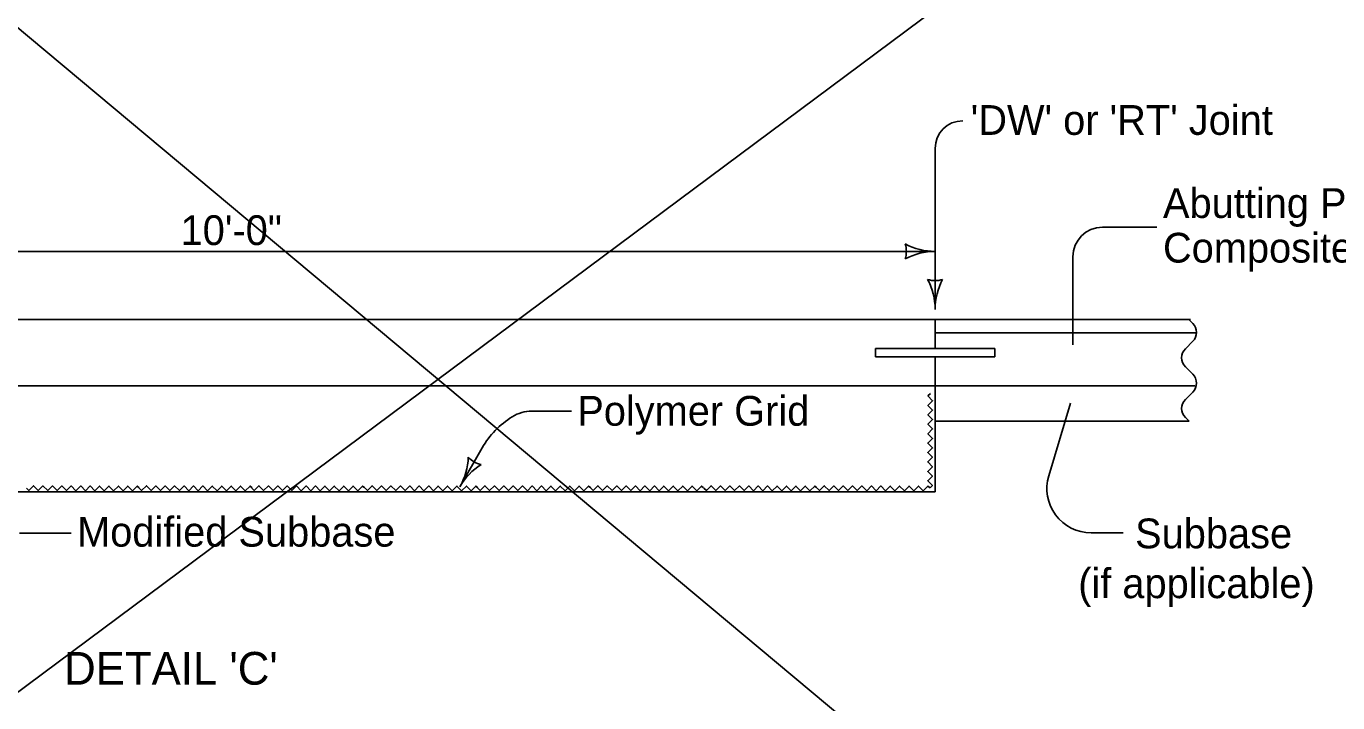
# Model space of a CAD drawing. Extents: x 8925 to 81668, y 4369 to 11918.
# Drawn here: x 14969 to 15851, y 5831 to 6286 of the extents above; entities that cross this region are included whole.
import ezdxf

# ---------------------------------------------------------------- set-up
doc = ezdxf.new("R2010")
doc.units = 0
for name, color, linetype in [('dsnShtPlotShapeBatchPrint', 7, 'Continuous'), ('dsnStdBorder', 7, 'Continuous'), ('SheetBorder', 7, 'Continuous')]:
    doc.layers.add(name, color=color, linetype=linetype)

msp = doc.modelspace()

# ---------------------------------------------------------------- linework, layer by layer
at = {"layer": 'dsnStdBorder'}
for p, q in [((15580.02, 6095.61), (15580.02, 6203.81)), ((15729, 6150.84), (15692.53, 6150.84)), ((14653.38, 6134.57), (15580.02, 6134.57)), ((15672.73, 6131.04), (15672.73, 6071.75)), ((15580.02, 6088.81), (14663.54, 6088.81)), ((14663.54, 6088.81), (15580.02, 6088.81)), ((15580.02, 6069.32), (15580.02, 6088.81)), ((15580.02, 6088.81), (15580.02, 6069.32)), ((15580.02, 6088.81), (15580.02, 6069.32)), ((15580.02, 6088.81), (15751.74, 6088.81)), ((15753.27, 6086.22), (15750.77, 6088.71)), ((15580.02, 6079.95), (15755.77, 6079.95)), ((15539.92, 6063.75), (15539.92, 6069.32)), ((15539.92, 6069.32), (15580.02, 6069.32)), ((15539.92, 6063.75), (15539.92, 6069.32)), ((15539.92, 6069.32), (15620.11, 6069.32)), ((15620.11, 6069.32), (15620.11, 6063.75)), ((15748.28, 6069.16), (15753.27, 6074.16)), ((15580.02, 6063.75), (15539.92, 6063.75)), ((15620.11, 6063.75), (15539.92, 6063.75)), ((15580.02, 6044.26), (15580.02, 6063.75)), ((15580.02, 6063.75), (15580.02, 6044.26)), ((15750.77, 6054.61), (15748.28, 6057.1)), ((15753.27, 6052.11), (15750.77, 6054.61)), ((14704.61, 6044.26), (15580.02, 6044.26)), ((14704.61, 6044.26), (15580.02, 6044.26)), ((15580.02, 6044.26), (15580.02, 6020.5)), ((15754.76, 6044.26), (15580.02, 6044.26)), ((15656.38, 5983.71), (15670.96, 6032.68)), ((15748.28, 6035.06), (15753.27, 6040.05)), ((15335.43, 6027.24), (15308.83, 6027.24)), ((15580.02, 6008.05), (15580.02, 6020.5)), ((15580.02, 6020.5), (15750.77, 6020.5)), ((15750.77, 6020.5), (15748.28, 6023)), ((15580.02, 5972.98), (15580.02, 6008.05)), ((15275.38, 6002.52), (15260.41, 5976.38)), ((14683.08, 5972.98), (15580.02, 5972.98)), ((14998.94, 5945.25), (14964.38, 5945.25)), ((15706.56, 5945.53), (15684.84, 5945.53))]:
    msp.add_line(p, q, dxfattribs=at)
for points in [[(15576.6, 5975.65), (15578.19, 5977.22), (15575.03, 5980.41), (15578.21, 5983.56), (15575.05, 5986.74), (15578.23, 5989.9), (15575.07, 5993.07), (15578.25, 5996.23), (15575.08, 5999.42), (15578.26, 6002.57), (15575.1, 6005.75), (15578.28, 6008.91), (15575.12, 6012.09), (15578.29, 6015.24), (15575.13, 6018.42), (15578.31, 6021.58), (15575.15, 6024.75), (15578.33, 6027.91), (15575.16, 6031.09), (15578.34, 6034.25), (15575.18, 6037.43), (15576.83, 6039.06)], [(14968.99, 5975.47), (14970.56, 5973.88), (14973.75, 5977.04), (14976.9, 5973.86), (14980.08, 5977.02), (14983.24, 5973.84), (14986.41, 5977), (14989.57, 5973.82), (14992.75, 5976.98), (14995.91, 5973.8), (14999.09, 5976.97), (15002.25, 5973.79), (15005.43, 5976.95), (15008.58, 5973.77), (15011.76, 5976.93), (15014.92, 5973.76), (15018.09, 5976.92), (15021.25, 5973.74), (15024.43, 5976.9), (15027.59, 5973.73), (15030.77, 5976.88), (15033.92, 5973.71), (15037.1, 5976.87), (15040.26, 5973.69), (15043.43, 5976.85), (15044.86, 5975.72)], [(15044.85, 5975.47), (15046.43, 5973.88), (15049.61, 5977.04), (15052.77, 5973.86), (15055.95, 5977.02), (15059.11, 5973.84), (15062.28, 5977), (15065.44, 5973.82), (15068.62, 5976.98), (15071.78, 5973.8), (15074.96, 5976.97), (15078.12, 5973.79), (15081.29, 5976.95), (15084.45, 5973.77), (15087.63, 5976.93), (15090.79, 5973.76), (15093.96, 5976.92), (15097.12, 5973.74), (15100.29, 5976.9), (15103.46, 5973.73), (15106.64, 5976.88), (15109.79, 5973.71), (15112.97, 5976.87), (15116.13, 5973.69), (15119.3, 5976.85), (15120.73, 5975.72)], [(15120.54, 5975.47), (15122.12, 5973.88), (15125.3, 5977.04), (15128.45, 5973.86), (15131.64, 5977.02), (15134.8, 5973.84), (15137.96, 5977), (15141.13, 5973.82), (15144.31, 5976.98), (15147.46, 5973.8), (15150.64, 5976.97), (15153.8, 5973.79), (15156.98, 5976.95), (15160.13, 5973.77), (15163.32, 5976.93), (15166.48, 5973.76), (15169.64, 5976.92), (15172.81, 5973.74), (15175.98, 5976.9), (15179.14, 5973.73), (15182.32, 5976.88), (15185.48, 5973.71), (15188.65, 5976.87), (15191.81, 5973.69), (15194.99, 5976.85), (15196.41, 5975.72)], [(15196.67, 5975.47), (15198.24, 5973.88), (15201.43, 5977.04), (15204.58, 5973.86), (15207.76, 5977.02), (15210.92, 5973.84), (15214.09, 5977), (15217.25, 5973.82), (15220.43, 5976.98), (15223.59, 5973.8), (15226.77, 5976.97), (15229.93, 5973.79), (15233.11, 5976.95), (15236.26, 5973.77), (15239.44, 5976.93), (15242.6, 5973.76), (15245.77, 5976.92), (15248.93, 5973.74), (15252.11, 5976.9), (15255.27, 5973.73), (15258.45, 5976.88), (15261.6, 5973.71), (15264.78, 5976.87), (15267.94, 5973.69), (15271.11, 5976.85), (15272.54, 5975.72)], [(15272.53, 5975.47), (15274.1, 5973.88), (15277.29, 5977.04), (15280.44, 5973.86), (15283.62, 5977.02), (15286.78, 5973.84), (15289.95, 5977), (15293.11, 5973.82), (15296.3, 5976.98), (15299.45, 5973.8), (15302.63, 5976.97), (15305.79, 5973.79), (15308.97, 5976.95), (15312.12, 5973.77), (15315.3, 5976.93), (15318.46, 5973.76), (15321.63, 5976.92), (15324.79, 5973.74), (15327.97, 5976.9), (15331.13, 5973.73), (15334.31, 5976.88), (15337.46, 5973.71), (15340.64, 5976.87), (15343.8, 5973.69), (15346.98, 5976.85), (15348.4, 5975.72)], [(15348.47, 5975.47), (15350.05, 5973.88), (15353.23, 5977.04), (15356.38, 5973.86), (15359.57, 5977.02), (15362.73, 5973.84), (15365.89, 5977), (15369.05, 5973.82), (15372.24, 5976.98), (15375.39, 5973.8), (15378.57, 5976.97), (15381.73, 5973.79), (15384.91, 5976.95), (15388.06, 5973.77), (15391.25, 5976.93), (15394.41, 5973.76), (15397.57, 5976.92), (15400.73, 5973.74), (15403.91, 5976.9), (15407.07, 5973.73), (15410.25, 5976.88), (15413.41, 5973.71), (15416.58, 5976.87), (15419.74, 5973.69), (15422.92, 5976.85), (15424.34, 5975.72)], [(15424.59, 5975.47), (15426.17, 5973.88), (15429.35, 5977.04), (15432.51, 5973.86), (15435.69, 5977.02), (15438.85, 5973.84), (15442.02, 5977), (15445.18, 5973.82), (15448.36, 5976.98), (15451.51, 5973.8), (15454.7, 5976.97), (15457.86, 5973.79), (15461.03, 5976.95), (15464.19, 5973.77), (15467.37, 5976.93), (15470.53, 5973.76), (15473.7, 5976.92), (15476.86, 5973.74), (15480.03, 5976.9), (15483.19, 5973.73), (15486.38, 5976.88), (15489.53, 5973.71), (15492.71, 5976.87), (15495.87, 5973.69), (15499.04, 5976.85), (15500.47, 5975.72)], [(15500.73, 5975.47), (15502.31, 5973.88), (15505.49, 5977.04), (15508.65, 5973.86), (15511.83, 5977.02), (15514.99, 5973.84), (15518.16, 5977), (15521.32, 5973.82), (15524.5, 5976.98), (15527.65, 5973.8), (15530.84, 5976.97), (15534, 5973.79), (15537.17, 5976.95), (15540.33, 5973.77), (15543.51, 5976.93), (15546.67, 5973.76), (15549.84, 5976.92), (15553, 5973.74), (15556.17, 5976.9), (15559.33, 5973.73), (15562.52, 5976.88), (15565.67, 5973.71), (15568.84, 5976.87), (15572.01, 5973.69), (15575.18, 5976.85), (15576.61, 5975.72)]]:
    msp.add_lwpolyline(points, dxfattribs=at)
for centre, radius, start, end in [((15598.58, 6203.81), 18.56, 90, 180), ((15692.53, 6131.04), 19.8, 90, 180), ((15544.18, 6134.58), 16.51, 342.26665, 17.73335), ((15580.02, 6177.32), 42.75, 241.92751, 270), ((15544.18, 6134.58), 16.51, 342.26665, 17.73335), ((15580.02, 6177.32), 42.75, 241.92751, 270), ((15580.02, 6091.83), 42.75, 90, 118.07249), ((15580.02, 6091.83), 42.75, 90, 118.07249), ((15580.02, 6131.46), 16.51, 252.26665, 287.73335), ((15537.27, 6095.61), 42.75, 360, 28.07249), ((15580.02, 6131.46), 16.51, 252.26665, 287.73335), ((15537.27, 6095.61), 42.75, 360, 28.07249), ((15622.77, 6095.61), 42.75, 151.92751, 180), ((15622.77, 6095.61), 42.75, 151.92751, 180), ((15747.25, 6080.19), 8.53, 315, 45), ((15754.31, 6063.13), 8.53, 135, 225), ((15747.25, 6046.08), 8.53, 315, 45), ((15754.31, 6029.03), 8.53, 135, 225), ((15308.83, 6002.24), 25, 90, 121.71831), ((15326.92, 5972.98), 59.4, 121.71831, 150.17827), ((15223.32, 5997.64), 42.75, 330.17945, 358.25194), ((15297.49, 5955.12), 42.75, 122.10696, 150.17945), ((15278.23, 6007.48), 16.51, 222.4461, 257.9128), ((15684.84, 5975.23), 29.7, 163.41722, 270)]:
    msp.add_arc(centre, radius, start, end, dxfattribs=at)
at = {"layer": 'SheetBorder'}
for p, q in [((13555.2, 7461.71), (17208.84, 4407.74)), ((17092.54, 7422.93), (13574.58, 4805.24))]:
    msp.add_line(p, q, dxfattribs=at)

# ---------------------------------------------------------------- texts
at = {"layer": 'dsnShtPlotShapeBatchPrint'}
for s, p in [("'DW' or 'RT' Joint", (15603.92, 6212.92)), ('Abutting PCC or', (15733.24, 6157.09)), ('10\'-0"', (15072.62, 6138.86)), ('Composite Pavement', (15733.24, 6127.09)), ('Polymer Grid', (15339.38, 6017.45)), ('Modified Subbase', (15003, 5936.18)), ('Subbase', (15714.5, 5935.06)), ('(if applicable)', (15676.23, 5901.55))]:
    msp.add_text(s, height=20, dxfattribs=at).set_placement(p)
at = {"layer": 'dsnStdBorder'}
msp.add_text("DETAIL 'C'", height=22, dxfattribs=at).set_placement((14994.29, 5843.39))

doc.saveas('drawing.dxf')
